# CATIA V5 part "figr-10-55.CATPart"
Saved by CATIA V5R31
Part number: Part1
Bounding box of the stored display mesh (mm): x -101.896 to 127.212, y -67.72 to 67.298, z 0 to 0
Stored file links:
  D:\PROJECTS\Project 2021\US EDITION\CATIA V5 6R 2021\Resources\Part Files\c10_catia_v5_6r2021_prt\c10_catia_v5_6r2021_prt\figr-10-55.CATPart
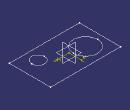
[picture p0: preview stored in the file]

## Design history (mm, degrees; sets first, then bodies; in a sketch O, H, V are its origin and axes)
Body1 (main body)
  Sketch1 on xy-plane, origin (0, 0, 0), H (1, 0, 0), V (0, 1, 0)
    line L1 (-101.8963, 67.298) -> (127.2122, 67.298)
    line L2 (127.2122, 67.298) -> (127.2122, -67.7199)
    line L3 (127.2122, -67.7199) -> (-101.8963, -67.7199)
    line L4 (-101.8963, -67.7199) -> (-101.8963, 67.298)
    horizontal: L1 H, L3 H
    vertical: L2 V, L4 V
  Sketch2 on xy-plane, origin (0, 0, 0), H (1, 0, 0), V (0, 1, 0)
    circle A1 centre (-45.2964, 9.2296) radius 39.3004
    circle A2 centre (71.0804, -29.9585) radius 20.9926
